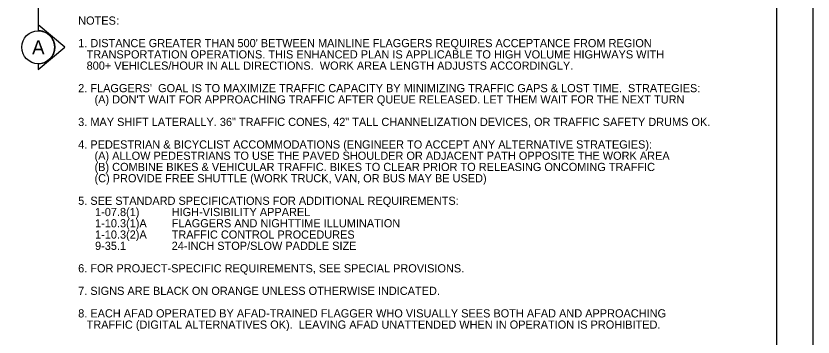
# Model space of a CAD drawing. Extents: x 99999.1 to 100095.7, y 99995 to 100010.7.
# Drawn here: x 100049.24 to 100056.06, y 100002.9 to 100005.65 of the extents above; entities that cross this region are included whole.
import ezdxf

# ---------------------------------------------------------------- set-up
doc = ezdxf.new("R2010")
doc.units = 0
for name, color, linetype in [('SH_GI_GeneralNotesBodyText', 7, 'Continuous'), ('SH_GI_PlotLimits', 7, 'Continuous'), ('SH_GI_SheetBorder', 7, 'Continuous'), ('SH_TI_WZSectionCut', 7, 'Continuous')]:
    doc.layers.add(name, color=color, linetype=linetype)

msp = doc.modelspace()

# ---------------------------------------------------------------- linework, layer by layer
at = {"layer": 'SH_GI_PlotLimits'}
msp.add_lwpolyline([(100039.0625, 99999.6875), (100056.0625, 99999.6875), (100056.0625, 100010.6875), (100039.0625, 100010.6875)], close=True, dxfattribs=at)
at = {"layer": 'SH_GI_SheetBorder'}
msp.add_line((100055.75, 100010.375), (100055.75, 100000), dxfattribs=at)
at = {"layer": 'SH_TI_WZSectionCut'}
for p, q in [((100049.4338, 100007.7022), (100049.4338, 100005.5723)), ((100049.4337, 100005.5723), (100049.4337, 100005.5224)), ((100049.6619, 100005.3812), (100049.4337, 100005.5723)), ((100049.4337, 100005.1901), (100049.6619, 100005.3812)), ((100049.4337, 100005.24), (100049.4337, 100005.1901))]:
    msp.add_line(p, q, dxfattribs=at)
msp.add_circle((100049.4338, 100005.3812), 0.1412, dxfattribs=at)
msp.add_arc((100049.4338, 100005.3812), 0.1412, 269.99779, 90.00221, dxfattribs=at)

# ---------------------------------------------------------------- texts
at = {"layer": 'SH_GI_GeneralNotesBodyText'}
for s, p in [('NOTES', (100049.7751, 100005.5743)), (':', (100050.1026, 100005.5743)), ("1. DISTANCE GREATER THAN 500' BETWEEN MAINLINE FLAGGERS REQUIRES ACCEPTANCE FROM REGION ", (100049.7751, 100005.3818)), ('TRANSPORTATION OPERATIONS. THIS ENHANCED PLAN IS APPLICABLE TO HIGH VOLUME HIGHWAYS WITH     ', (100049.8473, 100005.2856)), ('800+ VEHICLES/HOUR IN ALL DIRECTIONS.  WORK AREA LENGTH ADJUSTS ACCORDINGLY.', (100049.8473, 100005.1893)), ("2. FLAGGERS'  GOAL IS TO MAXIMIZE TRAFFIC CAPACITY BY MINIMIZING TRAFFIC GAPS & LOST TIME.  STRATEGIES:", (100049.7751, 100004.9968)), ("(A) DON'T WAIT FOR APPROACHING TRAFFIC AFTER QUEUE RELEASED. LET THEM WAIT FOR THE NEXT TURN", (100049.9151, 100004.9006)), ('3. MAY SHIFT LATERALLY. 36" TRAFFIC CONES, 42" TALL CHANNELIZATION DEVICES, OR TRAFFIC SAFETY DRUMS OK.', (100049.7751, 100004.7081)), ('4. PEDESTRIAN & BICYCLIST ACCOMMODATIONS (ENGINEER TO ACCEPT ANY ALTERNATIVE STRATEGIES):', (100049.7751, 100004.5156)), ('(A) ALLOW PEDESTRIANS TO USE THE PAVED SHOULDER OR ADJACENT PATH OPPOSITE THE WORK AREA', (100049.9151, 100004.4193)), ('(B) COMBINE BIKES & VEHICULAR TRAFFIC. BIKES TO CLEAR PRIOR TO RELEASING ONCOMING TRAFFIC', (100049.9151, 100004.3231)), ('(C) PROVIDE FREE SHUTTLE (WORK TRUCK, VAN, OR BUS MAY BE USED)', (100049.9151, 100004.2268)), ('5. SEE STANDARD SPECIFICATIONS FOR ADDITIONAL REQUIREMENTS:', (100049.7751, 100004.0343)), ('1-07.8(1) ', (100049.9195, 100003.9381)), ('HIGH-VISIBILITY APPAREL', (100050.5751, 100003.9381)), ('1-10.3(1)A ', (100049.9195, 100003.8418)), ('FLAGGERS AND NIGHTTIME ILLUMINATION', (100050.5751, 100003.8418)), ('1-10.3(2)A', (100049.9195, 100003.7456)), ('TRAFFIC CONTROL PROCEDURES', (100050.5751, 100003.7456)), ('9-35.1', (100049.9195, 100003.6493)), ('24-INCH STOP/SLOW PADDLE SIZE', (100050.5751, 100003.6493)), ('6. FOR PROJECT-SPECIFIC REQUIREMENTS, SEE SPECIAL PROVISIONS.', (100049.7751, 100003.4568)), ('7. SIGNS ARE BLACK ON ORANGE UNLESS OTHERWISE INDICATED.', (100049.7751, 100003.2643)), ('8. EACH AFAD OPERATED BY AFAD-TRAINED FLAGGER WHO VISUALLY SEES BOTH AFAD AND APPROACHING ', (100049.7751, 100003.0718)), ('TRAFFIC (DIGITAL ALTERNATIVES OK).  LEAVING AFAD UNATTENDED WHEN IN OPERATION IS PROHIBITED.', (100049.8473, 100002.9756))]:
    msp.add_text(s, height=0.07, rotation=360, dxfattribs=at).set_placement(p)
at = {"layer": 'SH_TI_WZSectionCut'}
msp.add_text('A', height=0.12, rotation=0.00995, dxfattribs=at).set_placement((100049.3808, 100005.3203))

doc.saveas('drawing.dxf')
